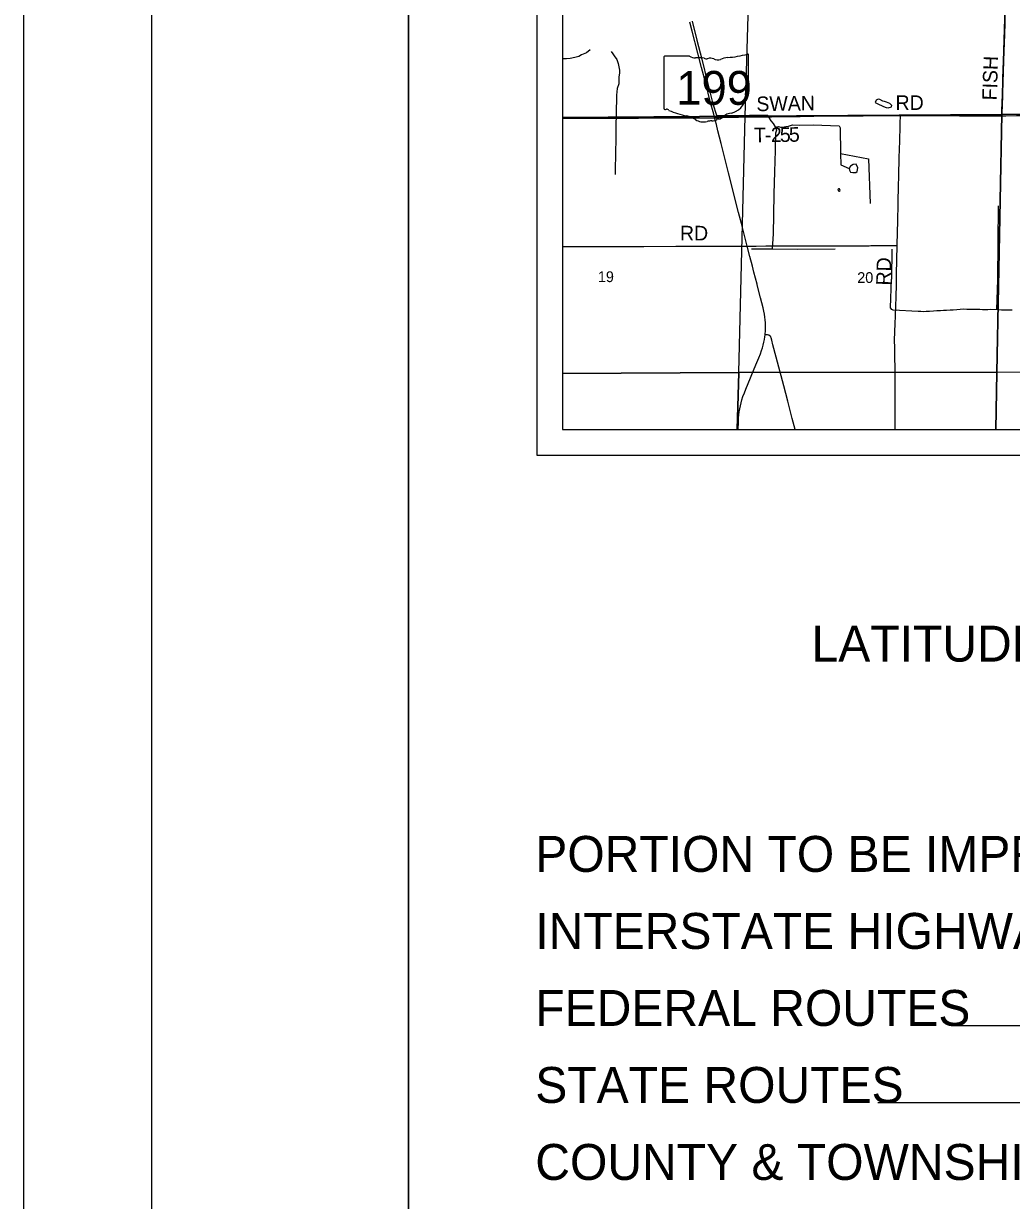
# Model space of a CAD drawing. Extents: x -8.3 to 42.1, y 0 to 22.
# Drawn here: x 0 to 3.85, y 11.097 to 15.682 of the extents above; entities that cross this region are included whole.
import ezdxf

# ---------------------------------------------------------------- set-up
doc = ezdxf.new("R2010")
doc.units = 0
for name, color, linetype in [('Default', 7, 'Continuous'), ('GM_X_County_Road', 7, 'Continuous'), ('GM_X_Minor_Lake', 7, 'Continuous'), ('GM_X_Minor_River', 7, 'Continuous'), ('GM_X_Section', 7, 'Continuous'), ('GM_X_Section_Text', 7, 'Continuous'), ('GM_X_State_Location', 7, 'Continuous'), ('GM_X_State_Route', 7, 'Continuous'), ('GM_X_State_Shield', 7, 'Continuous'), ('GM_X_Township_Road', 7, 'Continuous'), ('GM_X_Township_Road_Text', 7, 'Continuous'), ('SH_Border', 7, 'Continuous'), ('SH_Cut_Line', 7, 'Continuous'), ('SH_Data', 7, 'Continuous'), ('SH_Text', 7, 'Continuous')]:
    doc.layers.add(name, color=color, linetype=linetype)

msp = doc.modelspace()

# ---------------------------------------------------------------- linework, layer by layer
at = {"layer": 'Default'}
for points in [[(2.1, 16.3231), (2.1, 15.3156), (2.8124, 15.3208), (2.8424, 16.322)], [(2.1, 15.3156), (2.1, 14.3184), (2.7875, 14.322), (2.8124, 15.3208)], [(2.1, 14.3184), (2.1, 14.1), (2.7817, 14.1), (2.7875, 14.322)], [(2.7817, 14.1), (3.7889, 14.1), (3.7926, 14.3222), (2.7875, 14.322)], [(3.7889, 14.1), (4.7944, 14.1), (4.8014, 14.3239), (3.7926, 14.3222)]]:
    msp.add_lwpolyline(points, close=True, dxfattribs=at)
at = {"layer": 'GM_X_County_Road'}
msp.add_lwpolyline([(3.0074, 14.1), (2.996, 14.1436), (2.9787, 14.2099), (2.9628, 14.27), (2.9332, 14.3813), (2.9204, 14.4295), (2.9157, 14.4475), (2.9133, 14.4566), (2.9122, 14.4597), (2.9109, 14.4631), (2.909, 14.4654), (2.9058, 14.4674), (2.9029, 14.4682), (2.8994, 14.4685), (2.8962, 14.4686), (2.8898, 14.4689)], dxfattribs=at)
at = {"layer": 'GM_X_Minor_Lake'}
for p, q in [((3.3637, 15.3752), (3.3556, 15.3773)), ((3.2231, 15.1025), (3.2324, 15.1007)), ((3.1742, 15.033), (3.1749, 15.0296))]:
    msp.add_line(p, q, dxfattribs=at)
for points in [[(3.3556, 15.3773), (3.3486, 15.3798), (3.3378, 15.3851), (3.3306, 15.3868), (3.3225, 15.3825), (3.3196, 15.3738), (3.3271, 15.3702), (3.351, 15.3585), (3.3616, 15.3544), (3.3702, 15.353), (3.3821, 15.3568), (3.3842, 15.3625), (3.3757, 15.3703), (3.3637, 15.3752)], [(3.2324, 15.1007), (3.2431, 15.1007), (3.2486, 15.1052), (3.2516, 15.1191), (3.2448, 15.1342), (3.233, 15.1326), (3.2226, 15.1264), (3.2178, 15.1167), (3.2191, 15.1106), (3.2231, 15.1025)], [(3.1749, 15.0296), (3.1781, 15.0288), (3.1827, 15.0314), (3.1806, 15.0383), (3.1764, 15.0376), (3.1741, 15.0354), (3.1742, 15.033)]]:
    msp.add_lwpolyline(points, dxfattribs=at)
at = {"layer": 'GM_X_Minor_River'}
for points in [[(2.6059, 15.6909), (2.6239, 15.617), (2.6431, 15.5434), (2.6659, 15.4519), (2.6859, 15.3692), (2.7002, 15.3243), (2.759, 15.323), (2.8296, 15.324), (2.9003, 15.3246), (2.9056, 15.3135), (2.9118, 15.3023), (2.921, 15.2921), (2.9308, 15.2766), (2.9339, 15.2663), (2.9302, 15.255), (2.9294, 15.1869), (2.9267, 15.1045), (2.9242, 15.0186), (2.9223, 14.9369), (2.9209, 14.8621), (2.9174, 14.8044)], [(2.2083, 15.5791), (2.1935, 15.5673), (2.1751, 15.5591), (2.1636, 15.5537), (2.1479, 15.5492), (2.1303, 15.5452), (2.1155, 15.5445), (2.1, 15.5441)], [(2.2898, 15.5733), (2.2967, 15.564), (2.3018, 15.5555), (2.3116, 15.5419), (2.3176, 15.5254), (2.3199, 15.5135), (2.3222, 15.5005), (2.3226, 15.4887), (2.3203, 15.4736), (2.3196, 15.447), (2.3141, 15.4281), (2.3114, 15.402), (2.3112, 15.3788), (2.3096, 15.3515), (2.3092, 15.3241), (2.3078, 15.2876), (2.3079, 15.2378), (2.3068, 15.1728), (2.3063, 15.1135), (2.3057, 15.093)], [(2.9308, 15.2766), (2.9354, 15.2795), (2.9423, 15.2805), (2.9498, 15.2776), (2.9581, 15.2774), (2.9707, 15.28), (2.9818, 15.2824), (2.9964, 15.2865), (3.0241, 15.2861), (3.0768, 15.2869), (3.1792, 15.2832), (3.1824, 15.2759), (3.1837, 15.1747), (3.1851, 15.1309), (3.2178, 15.1167)], [(3.1837, 15.1747), (3.2932, 15.1541), (3.3, 14.9801)], [(3.7972, 14.6845), (3.7998, 14.9717)], [(2.8369, 14.804), (2.8915, 14.8036), (2.9174, 14.8044), (3.0168, 14.8031), (3.1629, 14.8034)], [(3.3842, 14.8028), (3.382, 14.6861)], [(3.486, 14.5593), (3.3897, 14.5644), (3.3837, 14.5675), (3.3793, 14.5745), (3.382, 14.6861)], [(3.7926, 14.5663), (3.7972, 14.6845)], [(3.8529, 14.5649), (3.8381, 14.565), (3.8236, 14.5647), (3.8115, 14.565), (3.7974, 14.5662), (3.7682, 14.567), (3.7587, 14.5669), (3.748, 14.5665), (3.7378, 14.5664), (3.7275, 14.5671), (3.7135, 14.5675), (3.7021, 14.5671), (3.6911, 14.5678), (3.6767, 14.5682), (3.6641, 14.5689), (3.6504, 14.5678), (3.6375, 14.5667), (3.6234, 14.5655), (3.6112, 14.5648), (3.5975, 14.564), (3.5853, 14.5632), (3.5735, 14.5624), (3.5598, 14.5625), (3.5465, 14.5613), (3.5309, 14.5599), (3.5183, 14.5595), (3.5069, 14.5591), (3.4967, 14.5594), (3.486, 14.5593)]]:
    msp.add_lwpolyline(points, dxfattribs=at)
at = {"layer": 'GM_X_Section'}
for points in [[(3.8435, 16.3264), (3.8127, 15.327), (2.8124, 15.3208), (2.8424, 16.322)], [(3.8435, 16.3264), (4.8464, 16.3395), (4.8204, 15.3344), (3.8127, 15.327)], [(2.8124, 15.3208), (3.8127, 15.327), (3.7926, 14.3222), (2.7875, 14.322)], [(4.8204, 15.3344), (4.8014, 14.3239), (3.7926, 14.3222), (3.8127, 15.327)]]:
    msp.add_lwpolyline(points, close=True, dxfattribs=at)
at = {"layer": 'GM_X_State_Route'}
for points in [[(2.6934, 15.3141), (2.6896, 15.3288), (2.6765, 15.3783), (2.6591, 15.4477), (2.6427, 15.5109), (2.6284, 15.5666), (2.6062, 15.6524), (2.597, 15.6869)], [(2.859, 14.6642), (2.8585, 14.6661), (2.8467, 14.7128), (2.8406, 14.7369), (2.831, 14.7745), (2.8207, 14.8147), (2.8129, 14.8453), (2.7981, 14.9025), (2.7868, 14.9461), (2.7477, 15.0998), (2.7371, 15.142), (2.7187, 15.2143), (2.7062, 15.264), (2.7, 15.2881), (2.6934, 15.3141)], [(2.7849, 14.1), (2.7858, 14.1294), (2.7867, 14.1449), (2.7878, 14.1572), (2.7894, 14.1695), (2.7912, 14.1802), (2.7936, 14.1924), (2.7965, 14.2044), (2.8, 14.2163), (2.8039, 14.2281), (2.8092, 14.2427), (2.8149, 14.2571), (2.8543, 14.3518), (2.8656, 14.3791), (2.8717, 14.3951), (2.8764, 14.4083), (2.8797, 14.4187), (2.8827, 14.4292), (2.8852, 14.4398), (2.8873, 14.4505), (2.8889, 14.4613), (2.8898, 14.4689), (2.8902, 14.4722), (2.8911, 14.483), (2.8916, 14.494), (2.8916, 14.5049), (2.8912, 14.5158), (2.8903, 14.5267), (2.889, 14.5375), (2.8871, 14.5498), (2.8851, 14.5605), (2.882, 14.5742), (2.8722, 14.6134), (2.859, 14.6642)]]:
    msp.add_lwpolyline(points, dxfattribs=at)
at = {"layer": 'GM_X_State_Shield'}
for p, q in [((2.4958, 15.5509), (2.4958, 15.3508)), ((2.5956, 15.5544), (2.4991, 15.5544)), ((2.8254, 15.4546), (2.8254, 15.5593)), ((2.8254, 15.4547), (2.8254, 15.4546))]:
    msp.add_line(p, q, dxfattribs=at)
for centre, major_axis, start_param, end_param in [((2.4996, 15.5513), (0.00382, 0), 1.712693, 3.28349), ((2.6186, 15.5776), (0.037, 0), 4.042523, 4.731795), ((2.6309, 15.442), (0.133, 0), 1.404758, 1.657858), ((2.661, 15.5524), (0.0107, 0), 3.836095, 5.185415), ((2.6767, 15.5292), (0.0222, 0), 0.950623, 2.079405), ((2.7054, 15.561), (0.0267, 0), 4.081561, 5.145723), ((2.7526, 15.4932), (0.0703, 0), 1.699011, 2.107814), ((2.708, 15.8272), (0.3495, 0), 4.814394, 5.042369), ((2.8218, 15.5598), (0.00367, 0), 6.141152, 7.989035), ((2.8246, 15.4469), (0.00568, 0), 1.883978, 3.671073), ((2.8215, 15.4542), (0.00393, 0), 5.05454, 6.418171), ((2.7276, 15.3975), (0.0874, 0), 5.101752, 6.440018), ((2.8386, 15.4108), (0.0248, 0), 2.387724, 3.262537), ((2.7884, 15.4337), (0.0341, 0), 5.934695, 6.695948), ((2.4996, 15.3504), (0.00385, 0), 3.00124, 4.508301), ((2.5002, 15.3708), (0.0294, 0), 4.665946, 4.897461), ((2.5062, 15.3392), (0.0106, 0), 0.519207, 1.627899), ((2.6401, 15.519), (0.2524, 0), 4.195997, 4.488961), ((2.5648, 15.2609), (0.079, 0), 0.823519, 1.323587), ((2.7038, 15.3314), (0.0282, 0), 4.937069, 5.64225), ((2.7644, 15.2946), (0.0479, 0), 1.647645, 2.488434), ((2.6502, 15.3383), (0.0501, 0), 4.026481, 4.996735), ((2.6792, 15.2691), (0.0412, 0), 1.495662, 1.94098), ((2.6828, 15.3233), (0.0267, 0), 4.691044, 5.507374), ((2.707, 15.3039), (0.00752, 0), 1.147584, 2.315152)]:
    msp.add_ellipse(centre, major_axis=major_axis, ratio=0.8, start_param=start_param, end_param=end_param, dxfattribs=at)
at = {"layer": 'GM_X_Township_Road'}
for points in [[(2.1, 20.9), (2.1, 15.312), (2.6931, 15.3146), (2.6982, 15.315), (2.6999, 15.3151), (2.7044, 15.3154), (2.7248, 15.3156), (2.7868, 15.3169), (2.8723, 15.3184), (2.9143, 15.3189), (2.9623, 15.3196), (3.0066, 15.3201), (3.0265, 15.3204), (3.0448, 15.3211), (3.0791, 15.3218), (3.1039, 15.322), (3.1148, 15.322), (3.1239, 15.322), (3.1284, 15.3221), (3.1469, 15.3223), (3.164, 15.3226), (3.1833, 15.3226), (3.203, 15.3226), (3.2234, 15.3225), (3.2714, 15.3232), (3.2933, 15.3233), (3.321, 15.3237), (3.3583, 15.3237), (3.3832, 15.3235), (3.4112, 15.3238), (3.4172, 15.3238), (3.436, 15.324), (3.4998, 15.3236), (3.5231, 15.3236), (3.5542, 15.3234), (3.5946, 15.3234), (3.6475, 15.3232), (3.7237, 15.3232), (3.7719, 15.323), (3.8061, 15.3229), (3.812, 15.3229), (3.8123, 15.3284), (3.8131, 15.3471), (3.8146, 15.3937), (3.8171, 15.4683), (3.8179, 15.5025), (3.8189, 15.5368), (3.8202, 15.5741), (3.8224, 15.6394), (3.8238, 15.683)], [(3.8238, 15.683), (3.8224, 15.6394), (3.8202, 15.5741), (3.8189, 15.5368), (3.8179, 15.5025), (3.8171, 15.4683), (3.8146, 15.3937), (3.8131, 15.3471), (3.8123, 15.3284), (3.812, 15.3229), (3.8061, 15.3229), (3.7719, 15.323), (3.7237, 15.3232), (3.6475, 15.3232), (3.5946, 15.3234), (3.5542, 15.3234), (3.5231, 15.3236), (3.4998, 15.3236), (3.436, 15.324), (3.4172, 15.3238), (3.4112, 15.3238), (3.3832, 15.3235), (3.3583, 15.3237), (3.321, 15.3237), (3.2933, 15.3233), (3.2714, 15.3232), (3.2234, 15.3225), (3.203, 15.3226), (3.1833, 15.3226), (3.164, 15.3226), (3.1469, 15.3223), (3.1284, 15.3221), (3.1239, 15.322), (3.1148, 15.322), (3.1039, 15.322), (3.0791, 15.3218), (3.0448, 15.3211), (3.0265, 15.3204), (3.0066, 15.3201), (2.9623, 15.3196), (2.9143, 15.3189), (2.8723, 15.3184), (2.7868, 15.3169), (2.7248, 15.3156), (2.7044, 15.3154), (2.6999, 15.3151), (2.6982, 15.315), (2.6931, 15.3146), (2.1, 15.312), (2.1, 14.1), (7.8013, 14.1)], [(3.8122, 15.3224), (3.8125, 15.3279), (3.8134, 15.3465), (3.8148, 15.3932), (3.8174, 15.4678), (3.8181, 15.502), (3.8191, 15.5362), (3.8205, 15.5735), (3.8226, 15.6389), (3.824, 15.6824)], [(2.6934, 15.3141), (2.6985, 15.3144), (2.7001, 15.3145), (2.7047, 15.3148), (2.725, 15.315), (2.787, 15.3164), (2.8726, 15.3178), (2.9145, 15.3184), (2.9626, 15.319), (3.0068, 15.3196), (3.0267, 15.3199), (3.045, 15.3206), (3.0794, 15.3212), (3.1041, 15.3214), (3.115, 15.3214), (3.1241, 15.3214), (3.1286, 15.3216), (3.1471, 15.3218), (3.1642, 15.322), (3.1835, 15.3221), (3.2032, 15.3221), (3.2236, 15.3219), (3.2717, 15.3226), (3.2935, 15.3228), (3.3113, 15.323)], [(3.3113, 15.323), (3.3212, 15.3231), (3.3585, 15.3231), (3.3834, 15.323), (3.4114, 15.3232), (3.4174, 15.3233)], [(3.4052, 14.8171), (3.4053, 14.8192), (3.4075, 14.9139), (3.4078, 14.9279), (3.4086, 14.9637), (3.4085, 14.9792), (3.4084, 14.9901), (3.4085, 14.9978), (3.4087, 15.0087), (3.4093, 15.0258), (3.4102, 15.0475), (3.4112, 15.0864), (3.4118, 15.1097), (3.4124, 15.1392), (3.4128, 15.1578), (3.413, 15.1671), (3.4134, 15.1827), (3.415, 15.2324), (3.4162, 15.2743), (3.4167, 15.2976), (3.4173, 15.3177), (3.4174, 15.3233)], [(3.4174, 15.3233), (3.4363, 15.3234), (3.5, 15.3231), (3.5233, 15.323), (3.5544, 15.3228), (3.5948, 15.3228), (3.6477, 15.3226), (3.7239, 15.3226), (3.7721, 15.3225), (3.8063, 15.3224), (3.8122, 15.3224)], [(3.8122, 15.3224), (3.8281, 15.3223), (3.87, 15.3229), (3.9027, 15.3236), (3.9245, 15.3239), (3.9432, 15.3242), (3.9726, 15.3249), (4.0177, 15.3258), (4.0456, 15.3264), (4.0878, 15.327), (4.1328, 15.3276), (4.2026, 15.3295), (4.3223, 15.3316), (4.3628, 15.3322), (4.4141, 15.3328), (4.4716, 15.3335), (4.5354, 15.3338), (4.5913, 15.3342), (4.6939, 15.3344), (4.7375, 15.3347), (4.7795, 15.3351), (4.8183, 15.3353), (4.8231, 15.3353)], [(2.1, 14.8131), (2.1158, 14.8131), (2.262, 14.8133), (2.3522, 14.8134), (2.4175, 14.8136), (2.5419, 14.8138), (2.6445, 14.8142), (2.7129, 14.8145), (2.8093, 14.8147), (2.815, 14.8148), (2.8207, 14.8147)], [(2.8207, 14.8147), (2.8231, 14.8147), (2.8322, 14.8146), (2.8552, 14.8149), (2.8924, 14.8152), (2.9452, 14.8155), (2.9948, 14.8162), (3.0321, 14.8161), (3.0662, 14.8159), (3.1035, 14.8156), (3.1159, 14.8155), (3.1625, 14.8155), (3.2057, 14.8156), (3.2181, 14.8157), (3.2305, 14.8159), (3.2429, 14.8161), (3.2646, 14.8162), (3.277, 14.8161), (3.2924, 14.8161), (3.2955, 14.8161), (3.3015, 14.8163), (3.3076, 14.8164), (3.3199, 14.8165), (3.3323, 14.8167), (3.3633, 14.8169), (3.3912, 14.817), (3.4006, 14.8171), (3.4052, 14.8171)], [(3.3974, 14.1), (3.3974, 14.1232), (3.3974, 14.2087), (3.3974, 14.2522), (3.3972, 14.2942), (3.3971, 14.3175), (3.3966, 14.3455), (3.396, 14.375), (3.3953, 14.4107), (3.395, 14.4278), (3.3948, 14.4387), (3.3947, 14.448), (3.3949, 14.4573), (3.3953, 14.4712), (3.3957, 14.4836), (3.3967, 14.51), (3.3978, 14.5442), (3.3991, 14.5799), (3.4003, 14.6187), (3.4015, 14.6638), (3.4025, 14.7057), (3.4052, 14.8171)]]:
    msp.add_lwpolyline(points, dxfattribs=at)
at = {"layer": 'SH_Border'}
for points in [[(0.5, 21.5), (1.5, 21.5), (1.5, 0.5), (0.5, 0.5)], [(1.5, 21.5), (33.5, 21.5), (33.5, 0.5), (1.5, 0.5)]]:
    msp.add_lwpolyline(points, close=True, dxfattribs=at)
at = {"layer": 'SH_Cut_Line'}
msp.add_lwpolyline([(0, 0), (34, 0), (34, 22), (0, 22)], close=True, dxfattribs=at)
msp.add_lwpolyline([(2.1, 20.9), (2.1, 14.1), (7.8013, 14.1)], dxfattribs=at)
at = {"layer": 'SH_Data'}
for p, q in [((2, 21), (2, 14)), ((2.1, 20.9), (2.1, 14.1)), ((2.1, 14.1), (8.9, 14.1)), ((2.1, 14.1), (2.1, 14.1)), ((2, 14), (9, 14)), ((7.7, 11.7767), (3.6192, 11.7767)), ((7.7, 11.4767), (3.3288, 11.4767))]:
    msp.add_line(p, q, dxfattribs=at)

# ---------------------------------------------------------------- texts
at = {"layer": 'GM_X_Section_Text'}
for s, p in [('19', (2.2384, 14.6744)), ('20', (3.2492, 14.6711))]:
    msp.add_text(s, height=0.04186, rotation=0, dxfattribs=at).set_placement(p)
at = {"layer": 'GM_X_State_Location'}
msp.add_text('199', height=0.000189, rotation=0, dxfattribs=at).set_placement((2.5901, 15.4238))
for s in ['s', 'r']:
    msp.add_text(s, height=0.000189, dxfattribs=at).set_placement((2.6569, 15.4376))
at = {"layer": 'GM_X_State_Shield'}
msp.add_text('199', height=0.13184, dxfattribs=at).set_placement((2.5443, 15.3649))
at = {"layer": 'GM_X_Township_Road_Text'}
for s, height, rotation, p in [('FISH', 0.05682, 88.0975, (3.7927, 15.3815)), ('SWAN', 0.05682, 0.9228, (2.8565, 15.34)), ('RD', 0.05682, 0, (3.3984, 15.345)), ('T', 0.0568, 0.5957, (2.8469, 15.219)), ('2', 0.0568, 0.6388, (2.9128, 15.2197)), ('5', 0.0568, 0.7651, (2.9479, 15.2201)), ('5', 0.0568, 1.291, (2.9835, 15.2206)), ('-', 0.0568, 0.5992, (2.8894, 15.2195)), ('RD', 0.05682, 0, (2.5584, 14.8367)), ('RD', 0.05682, 88.5306, (3.3794, 14.6605))]:
    msp.add_text(s, height=height, rotation=rotation, dxfattribs=at).set_placement(p)
at = {"layer": 'SH_Text'}
for s, p in [('LATITUDE:  N41°24\'33"     LONGITUDE:  W83°27\'25"', (3.071, 13.1959)), ('PORTION TO BE IMPROVED', (1.9944, 12.3767)), ('INTERSTATE HIGHWAY', (1.9944, 12.0767)), ('FEDERAL ROUTES', (1.9944, 11.7767)), ('STATE ROUTES', (1.9944, 11.4767)), ('COUNTY & TOWNSHIP ROADS', (1.9944, 11.1767))]:
    msp.add_text(s, height=0.14, dxfattribs=at).set_placement(p)

doc.saveas('drawing.dxf')
